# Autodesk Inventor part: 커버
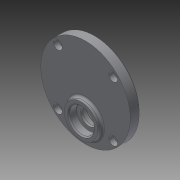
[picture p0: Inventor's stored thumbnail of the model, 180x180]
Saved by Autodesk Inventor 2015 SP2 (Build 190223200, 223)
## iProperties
Created: 2015-06
Part Number: 커버
Material: 일반
Document SubType Name: Modeling
Designer: AMC
Density: 1 g/cm^3
Appearance: 기본값
Author: AMC
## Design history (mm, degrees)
sketch "스케치1"
  geometry: C1 r 40 at (0, 0); 1 further point
  constraints: 1 centre point, 1 coincident
  dimensions: "d0" = 80 diameter of C1
extrude "돌출1" new body sketch "스케치1" distance "d1" = 9; taper "d2" = 0 deg
sketch "스케치2"
  geometry: C1 r 14 at (0, -20); C2 r 14 at (0, 11); 1 further point
  constraints: 2 centre point, 2 vertical alignment
  dimensions: "d3" = 28 diameter of C1; "d4" = 28 diameter of C2; "d5" = 31 distance of C1.centre C2.centre; "d6" = 20 distance of point (0, 0) C1.centre
extrude "돌출2" join sketch "스케치2" distance "d7" = 3; taper "d8" = 0 deg
sketch "스케치3"
  geometry: C1 r 15 at (0, -20); 1 further point
  constraints: 1 centre point, 1 vertical alignment
  dimensions: "d9" = 30 diameter of C1; "d10" = 20 distance of C1.centre point (0, 0)
extrude "돌출3" join sketch "스케치3" distance "d11" = 4; taper "d12" = 0 deg
sketch "스케치4"
  geometry: C1 r 11 at (0, 0); 1 further point
  constraints: 1 centre point, 1 vertical alignment
  dimensions: "d13" = 22 diameter of C1; "d14" = 20 distance of C1.centre point (0, 20)
extrude "돌출4" cut sketch "스케치4" distance "d15" = 7; taper "d16" = 0 deg
sketch "스케치5"
  geometry: C1 r 11 at (0, 0); 1 further point
  constraints: 1 centre point, 1 vertical alignment
  dimensions: "d17" = 22 diameter of C1; "d18" = 20 distance of C1.centre point (0, 20)
extrude "돌출5" cut sketch "스케치5" distance "d19" = 7; taper "d20" = 0 deg
sketch "스케치6"
  geometry: C1 r 7.5 at (0, 0); C2 r 11 at (0, 0) reference; C3 r 40 at (0, 20) reference; 1 further point
  constraints: 1 centre point, 1 vertical alignment
  dimensions: "d21" = 15 diameter of C1; "d22" = 20 distance of point (0, 20) C1.centre
extrude "돌출6" cut sketch "스케치6" stored distance "d23" = 7; taper "d24" = 0 deg
sketch "스케치7"
  geometry: C1 r 11 at (0, 0); 1 further point
  constraints: 1 centre point, 1 vertical alignment
  dimensions: "d25" = 22 diameter of C1; "d26" = 11 distance of point (0, -11) C1.centre
extrude "돌출7" cut sketch "스케치7" distance "d27" = 7; taper "d28" = 0 deg
sketch "스케치8"
  geometry: C1 r 9 at (0, 0); 1 further point
  constraints: 1 centre point, 1 vertical alignment
  dimensions: "d29" = 18 diameter of C1; "d30" = 11 distance of point (0, -11) C1.centre
extrude "돌출8" cut sketch "스케치8" distance "d31" = 1; taper "d32" = 0 deg
chamfer "모따기1" distance "d33" = 1; stored, may be unused: second distance "d34" = 2, angle "d35" = 45 deg
fillet "모깎기1" dims "d36" = 2
fillet "모깎기2" dims "d37" = 2
chamfer "모따기2" distance "d38" = 1; stored, may be unused: second distance "d39" = 2, angle "d40" = 45 deg
fillet "모깎기3" dims "d41" = 0.3
sketch "스케치9" dims "d42" = 70
  geometry: L1 (0, 0)-(0, 30.871); L2 (0, 0)-(-24.749, 24.749); 2 further points
  constraints: 4 end point, 2 coincident, 1 vertical, 3 other
  dimensions: "d43" = 45 deg angle of L1 L2
hole "구멍1" sketch "스케치9" at (-24.749, 24.749) diameter "d44" = 4.5; stored, may be unused: countersink angle "d48" = 90 deg, drill point angle "d50" = 118 deg; dims "d45" = 6, "d46" = 8, "d47" = 4.4, "d49" = 8
fillet "모깎기4" dims "d54" = 2
node "솔리드1"
pattern_circular "원형 패턴1" dims angle "d52" = 360 deg
node "절단 모서리 투영1"
